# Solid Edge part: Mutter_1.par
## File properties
Sűrűség: 0,000 kg/m^3
Pontosság: 0,990
Author: ahadarics
Last saved by: ahadarics
Revision: 76
Username: ahadarics
Dokumentum tartalom típus: 0
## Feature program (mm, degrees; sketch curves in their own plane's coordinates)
base feature "unnamed BaseFeature 1"
thread "unnamed Thread 1"
chamfer "Letörés_1"  SetBackValue2 = 60 deg
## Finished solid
Body 1: solid body, 23 faces, 46 edges, 24 vertices.
  Faces by surface: cone 14, plane 8, cylinder 1
  Edges by curve: spline 24, circle 16, line 6
Bounding box of the edges (mm): 7.000 x 21.939 x 19.000, from (0, -10.9697, -9.5) to (7, 10.9697, 9.5).
Cylindrical faces by radius (mm): R5.3235 x1
Conical faces (half-angle, radius in mm at the cone's reference point): 60 deg R5.3235 x1, 60 deg R6.0163 x1, 60 deg R10.2348 x12
Planar faces by outward normal: +x 1, +z 1, -x 1, -z 1, oblique 4
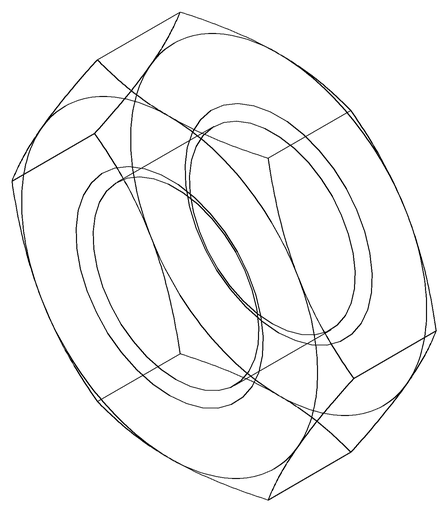
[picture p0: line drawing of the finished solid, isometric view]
